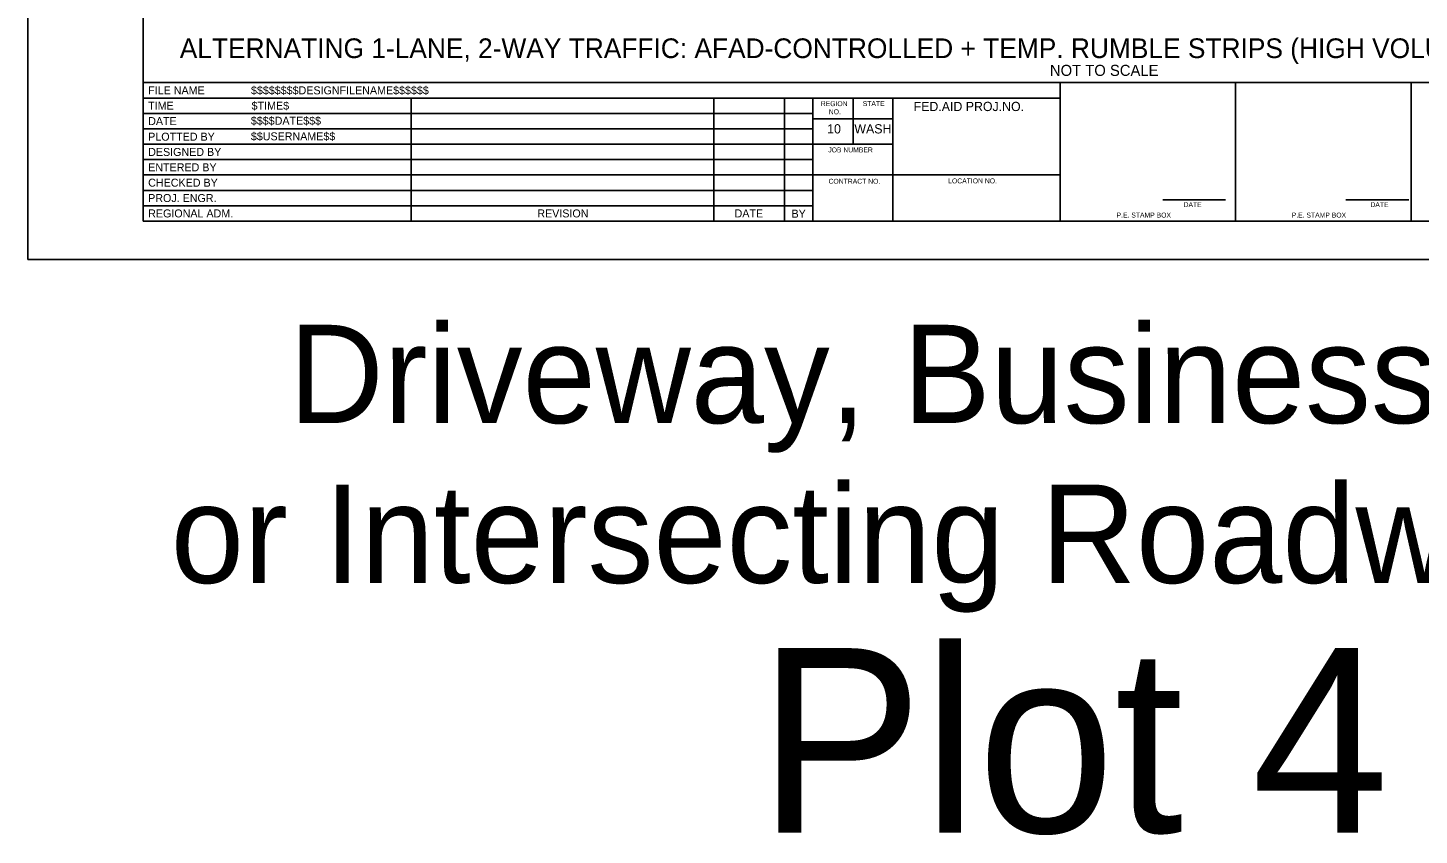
# Model space of a CAD drawing. Extents: x 99999.1 to 100095.7, y 99995 to 100010.7.
# Drawn here: x 100059.06 to 100070.38, y 99995.01 to 100001.57 of the extents above; entities that cross this region are included whole.
import ezdxf

# ---------------------------------------------------------------- set-up
doc = ezdxf.new("R2010")
doc.units = 0
for name, color, linetype in [('SH_DE_DetailHeading1Text', 7, 'Continuous'), ('SH_GI_PlotLimits', 7, 'Continuous'), ('SH_GI_SheetBorder', 7, 'Continuous'), ('SH_GI_SheetLocationText', 7, 'Continuous'), ('SH_GI_SheetTextInCells', 7, 'Continuous'), ('SH_GI_TitleBlockText', 7, 'Continuous')]:
    doc.layers.add(name, color=color, linetype=linetype)

msp = doc.modelspace()

# ---------------------------------------------------------------- linework, layer by layer
at = {"layer": 'SH_GI_PlotLimits'}
msp.add_lwpolyline([(100059.062, 99999.687), (100076.062, 99999.687), (100076.062, 100010.687), (100059.062, 100010.687)], close=True, dxfattribs=at)
at = {"layer": 'SH_GI_SheetBorder'}
for p, q in [((100060, 100010.375), (100060, 100000)), ((100060, 100001.126), (100075.75, 100001.126)), ((100067.457, 100000), (100067.457, 100001.126)), ((100068.883, 100000), (100068.883, 100001.126)), ((100070.309, 100001.126), (100070.309, 100000)), ((100060, 100001.001), (100067.457, 100001.001)), ((100062.179, 100001.001), (100062.179, 100000)), ((100064.641, 100001.001), (100064.641, 100000)), ((100065.216, 100001.001), (100065.216, 100000)), ((100065.445, 100001.001), (100065.445, 100000)), ((100065.772, 100000.625), (100065.772, 100001.001)), ((100066.096, 100000), (100066.096, 100001.001)), ((100060, 100000.876), (100062.182, 100000.876)), ((100062.182, 100000.876), (100065.447, 100000.876)), ((100066.096, 100000.831), (100065.447, 100000.831)), ((100060, 100000.751), (100062.182, 100000.751)), ((100062.182, 100000.751), (100065.447, 100000.751)), ((100060, 100000.625), (100065.447, 100000.625)), ((100066.096, 100000.625), (100065.447, 100000.625)), ((100060, 100000.5), (100065.447, 100000.5)), ((100060, 100000.375), (100065.447, 100000.375)), ((100067.457, 100000.375), (100065.447, 100000.375)), ((100060, 100000.25), (100065.447, 100000.25)), ((100060, 100000.125), (100065.447, 100000.125)), ((100068.29, 100000.173), (100068.802, 100000.173)), ((100069.78, 100000.173), (100070.291, 100000.173)), ((100060, 100000), (100075.75, 100000))]:
    msp.add_line(p, q, dxfattribs=at)

# ---------------------------------------------------------------- texts
at = {"layer": 'SH_DE_DetailHeading1Text'}
for s, height, p in [('ALTERNATING 1-LANE, 2-WAY TRAFFIC: AFAD-CONTROLLED + TEMP. RUMBLE STRIPS (HIGH VOLUME HIGHWAYS, 40 MPH OR LESS)', 0.16, (100060.298, 100001.326)), ('NOT TO SCALE', 0.09, (100067.373, 100001.181))]:
    msp.add_text(s, height=height, rotation=360, dxfattribs=at).set_placement(p)
at = {"layer": 'SH_GI_SheetLocationText'}
for s, height, p in [('Driveway, Business Access,', 0.8, (100061.184, 99998.357)), ('or Intersecting Roadway Details', 0.8, (100060.225, 99997.057)), ('Plot 4', 1.5, (100065.001, 99995.027))]:
    msp.add_text(s, height=height, dxfattribs=at).set_placement(p)
at = {"layer": 'SH_GI_SheetTextInCells'}
for s, height, p in [('FILE NAME', 0.0651, (100060.041, 100001.031)), ('TIME', 0.0651, (100060.041, 100000.906)), ('REGION', 0.04, (100065.51, 100000.935)), ('NO.', 0.04, (100065.575, 100000.869)), ('STATE', 0.04, (100065.851, 100000.936)), ('FED.AID PROJ.NO.', 0.07506, (100066.265, 100000.895)), ('DATE', 0.0651, (100060.041, 100000.781)), ('10', 0.0751, (100065.562, 100000.713)), ('WASH', 0.0751, (100065.783, 100000.713)), ('PLOTTED BY', 0.0651, (100060.041, 100000.654)), ('DESIGNED BY', 0.06505, (100060.041, 100000.53)), ('JOB NUMBER', 0.04, (100065.571, 100000.559)), ('ENTERED BY', 0.0651, (100060.041, 100000.405)), ('CHECKED BY', 0.0651, (100060.041, 100000.28)), ('CONTRACT NO.', 0.04003, (100065.573, 100000.304)), ('LOCATION NO.', 0.04003, (100066.546, 100000.307)), ('PROJ. ENGR.', 0.06505, (100060.041, 100000.155)), ('REGIONAL ADM.', 0.06505, (100060.041, 100000.03)), ('REVISION', 0.0651, (100063.205, 100000.03)), ('DATE', 0.04, (100068.46, 100000.114)), ('DATE', 0.04, (100069.979, 100000.114)), ('DATE', 0.0651, (100064.809, 100000.03)), ('BY', 0.0651, (100065.272, 100000.028)), ('P.E. STAMP BOX', 0.04003, (100067.915, 100000.029)), ('P.E. STAMP BOX', 0.04003, (100069.339, 100000.029))]:
    msp.add_text(s, height=height, dxfattribs=at).set_placement(p)
at = {"layer": 'SH_GI_TitleBlockText'}
for s, height, p in [('$$$$$$$$DESIGNFILENAME$$$$$$', 0.06505, (100060.877, 100001.031)), ('$TIME$', 0.0651, (100060.882, 100000.906)), ('$$$$DATE$$$', 0.06505, (100060.876, 100000.784)), ('$$USERNAME$$', 0.06505, (100060.876, 100000.657))]:
    msp.add_text(s, height=height, dxfattribs=at).set_placement(p)

doc.saveas('drawing.dxf')
